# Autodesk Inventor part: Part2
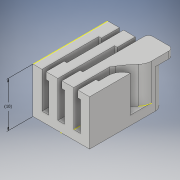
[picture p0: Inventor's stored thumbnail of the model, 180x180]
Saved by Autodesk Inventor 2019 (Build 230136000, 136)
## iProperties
Created: 2019-01
Part Number: Part2
Material: Generic
Document SubType Name: Modeling
Designer: Patel Family
Density: 1 g/cm^3
Appearance: Default
Author: Patel Family
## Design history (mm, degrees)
sketch "Sketch1"
  geometry: L1 (-6.25, 8.25)-(6.25, 8.25); L2 (6.25, 8.25)-(6.25, -8.25); L3 (6.25, -8.25)-(-6.25, -8.25); L4 (-6.25, -8.25)-(-6.25, 8.25); L5 (-6.25, 8.25)-(6.25, -8.25); L6 (6.25, 8.25)-(-6.25, -8.25); 1 further point
  constraints: 12 end point, 2 midpoint, 2 parallel, 1 horizontal, 1 perpendicular
  dimensions: "d0" = 12.5 distance of L2.end L3.end; "d1" = 16.5 distance between parallel lines of L3 L1
extrude "Extrusion1" new body sketch "Sketch1" distance "d2" = 2; taper "d3" = 0 deg
sketch "Sketch2"
  geometry: L1 (6.25, 8.25)-(-6.25, 8.25) reference; L2 (-6.25, 8.25)-(-4.25, 8.25); L3 (-4.25, 8.25)-(-2.75, 8.25); L4 (-2.75, 8.25)-(-0.75, 8.25); L5 (-0.75, 8.25)-(0.75, 8.25); L6 (0.75, 8.25)-(2.75, 8.25); L7 (2.75, 8.25)-(4.25, 8.25); L8 (4.25, 8.25)-(6.25, 8.25); L9 (-6.25, -8.25)-(6.25, -8.25) reference; L10 (-6.25, 8.25)-(-4.25, 8.25); L11 (-4.25, 8.25)-(-4.25, -8.25); L12 (-4.25, -8.25)-(-6.25, -8.25); L13 (-6.25, -8.25)-(-6.25, 8.25); L14 (-2.75, 8.25)-(-0.75, 8.25); L15 (-0.75, 8.25)-(-0.75, -8.25); L16 (-0.75, -8.25)-(-2.75, -8.25); L17 (-2.75, -8.25)-(-2.75, 8.25); L18 (0.75, 8.25)-(2.75, 8.25); L19 (2.75, 8.25)-(2.75, -8.25); L20 (2.75, -8.25)-(0.75, -8.25); L21 (0.75, -8.25)-(0.75, 8.25); L22 (6.25, -8.25)-(6.25, 8.25) reference; L23 (4.25, -8.25)-(6.25, -8.25); L24 (6.25, -8.25)-(6.25, 0.75); L25 (6.25, 0.75)-(4.25, 0.75); L26 (4.25, 0.75)-(4.25, -8.25); 1 further point
  constraints: 46 end point, 11 point on line, 8 parallel, 4 horizontal, 4 perpendicular, 1 collinear
  dimensions: "d4" = 2 distance of L1.end L2.end; "d5" = 1.5 distance of L2.end L3.end; "d6" = 2 distance of L3.end L4.end; "d7" = 1.5 distance of L4.end L5.end; "d8" = 2 distance of L5.end L6.end; "d9" = 1.5 distance of L6.end L7.end; "d10" = 9 distance of L24.end L23.end
extrude "Extrusion2" join sketch "Sketch2" distance "d11" = 8; taper "d12" = 0 deg
sketch "Sketch3"
  geometry: L1 (2.75, -8.25)-(2.75, 8.25) reference; L2 (6.25, 8.25)-(6.25, -8.25) reference; L3 (2.75, 2.436)-(6.25, 2.436); L4 (6.25, 2.436)-(6.25, 8.25); L5 (6.25, 8.25)-(2.75, 8.25); L6 (2.75, 8.25)-(2.75, 2.436); 1 further point
  constraints: 8 end point, 2 parallel, 1 horizontal, 1 perpendicular, 1 point on line
extrude "Extrusion3" join sketch "Sketch3" distance "d13" = 8; taper "d14" = 0 deg
sketch "Sketch4"
  geometry: L1 (5.5, 2)-(5.5, 10) reference; L2 (0, 0)-(0, 10) reference; L3 (5.5, 10)-(0, 10); L4 (0, 10)-(0, 8.5); L5 (0, 8.5)-(5.5, 8.5); L6 (5.5, 8.5)-(5.5, 10); 1 further point
  constraints: 8 end point, 2 parallel, 1 horizontal, 1 perpendicular, 1 point on line
  dimensions: "d15" = 1.5 distance of L4.end L3.end
extrude "Extrusion4" join sketch "Sketch4" distance "d16" = 2; taper "d17" = 0 deg
fillet "Fillet1" dims "d18" = 2
fillet "Fillet2" dims "d19" = 3
fillet "Fillet3" dims "d20" = 3
sketch "Sketch5"
  geometry: L1 (4.573, 2.744)-(2.75, 0); L2 (2.75, -8.25)-(2.75, 2.436) reference; L3 (2.75, 2.744)-(4.573, 2.744); A1 r 3 centre (3.25, 5.436) between (3.25, 2.436) and (6.25, 5.436) reference; 1 further point
  constraints: 4 end point, 1 horizontal, 1 point on circle, 1 point on line
sketch "Sketch6"
  geometry: 1 further point
sketch "Sketch7"
  geometry: L1 (4.675, 2.796)-(2.75, -0.348); L2 (2.75, -8.25)-(2.75, 2.436) reference; L3 (2.75, 2.796)-(4.675, 2.796); L4 (2.75, 2.796)-(2.75, -0.348); A1 r 3 centre (3.25, 5.436) between (3.25, 2.436) and (6.25, 5.436) reference; 1 further point
  constraints: 6 end point, 1 horizontal, 1 perpendicular, 1 point on circle, 1 point on line
extrude "Extrusion5" join sketch "Sketch7" distance "d21" = 8; taper "d22" = 0 deg
fillet "Fillet4" dims "d23" = 19.75
fillet "Fillet5" dims "d24" = 1
sketch "Sketch8"
  geometry: 1 further point
sketch "Sketch9"
  geometry: L1 (0, 10)-(16.5, 10) reference; L2 (16.5, 0)-(0, 0) reference; 1 further point
  dimensions: "d25" = 10 distance between parallel lines of L1 L2 (derived)
sketch "Sketch10"
  geometry: L1 (0, 8)-(16.5, 8) reference; L2 (16.5, 8)-(12.5, 8); L3 (12.5, 8)-(12.5, 6.5); L4 (12.5, 6.5)-(16.5, 6.5); L5 (16.5, 6.5)-(16.5, 8); 1 further point
  constraints: 8 end point, 2 parallel, 1 horizontal, 1 perpendicular
  dimensions: "d26" = 4 distance of L4.end L3.end; "d27" = 1.5 distance of L3.end L2.end
sketch "Sketch11"
  geometry: L1 (16.5, 0)-(16.5, 8) reference; L2 (16.5, 8)-(12.5, 8); L3 (12.5, 8)-(12.5, 6.5); L4 (12.5, 6.5)-(16.5, 6.5); L5 (16.5, 6.5)-(16.5, 8); 1 further point
  constraints: 8 end point, 2 parallel, 1 horizontal, 1 perpendicular
  dimensions: "d28" = 4 distance of L4.end L3.end; "d29" = 1.5 distance of L3.end L2.end
sketch "Sketch12"
  geometry: L1 (0, 8)-(-4, 8); L2 (-4, 8)-(-4, 6.5); L3 (-4, 6.5)-(0, 6.5); L4 (0, 6.5)-(0, 8); 1 further point
  constraints: 8 end point, 2 parallel, 1 horizontal, 1 perpendicular
  dimensions: "d30" = 4 distance of L3.end L2.end; "d31" = 1.5 distance of L2.end L1.end
sketch "Sketch13"
  geometry: L1 (0, 8)-(-4, 8); L2 (-4, 8)-(-4, 6.5); L3 (-4, 6.5)-(0, 6.5); L4 (0, 6.5)-(0, 8); 1 further point
  constraints: 8 end point, 2 parallel, 1 horizontal, 1 perpendicular
  dimensions: "d32" = 4 distance of L3.end L2.end; "d33" = 1.5 distance of L2.end L1.end
sketch "Sketch14"
  geometry: L1 (16.5, 0)-(16.5, 8) reference; L2 (16.5, 8)-(12.5, 8); L3 (12.5, 8)-(12.5, 6.5); L4 (12.5, 6.5)-(16.5, 6.5); L5 (16.5, 6.5)-(16.5, 8); 1 further point
  constraints: 8 end point, 2 parallel, 1 horizontal, 1 perpendicular
  dimensions: "d34" = 4 distance of L4.end L3.end; "d35" = 1.5 distance of L3.end L2.end
extrude "Extrusion6" join sketch "Sketch10" distance "d36" = 0.6; taper "d37" = 0 deg
extrude "Extrusion7" join sketch "Sketch11" distance "d38" = 0.6; taper "d39" = 0 deg
extrude "Extrusion8" join sketch "Sketch12" distance "d40" = 0.6; taper "d41" = 0 deg
extrude "Extrusion9" join sketch "Sketch13" distance "d42" = 0.6; taper "d43" = 0 deg
extrude "Extrusion10" join sketch "Sketch14" distance "d44" = 0.6; taper "d45" = 0 deg
sketch "Sketch15"
  geometry: 1 further point
sketch "Sketch16"
  geometry: 1 further point
sketch "Sketch17"
  geometry: 1 further point
sketch "Sketch18"
  geometry: 1 further point
body "Solid1"
